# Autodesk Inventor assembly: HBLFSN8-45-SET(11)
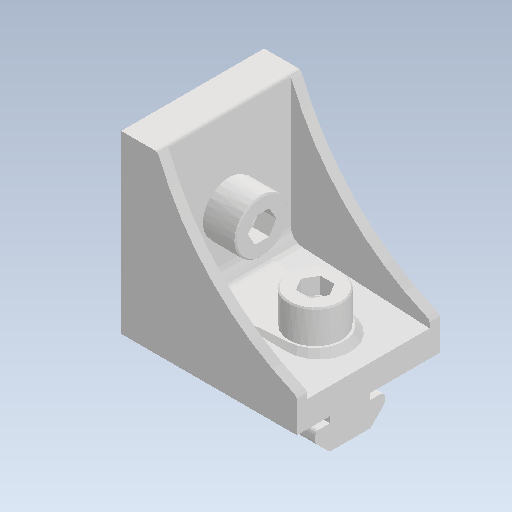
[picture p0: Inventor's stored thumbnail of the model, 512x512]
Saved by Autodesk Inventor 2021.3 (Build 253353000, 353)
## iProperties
Created: 2022-02
Part Number: HBLFSN8-45-SET(11)
Document SubType Name: Assembly
Designer: kengo
Author: kengo
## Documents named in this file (4)
- C:\Users\kengo\Documents\S2S_frame\SDC345\frame_misumi_ver12\HBLFSN8-45-SET(11).iam
- C:\Users\kengo\Documents\S2S_frame\SDC345\frame_misumi_ver12\HBLFSN8-45.ipt
- C:\Users\kengo\Documents\S2S_frame\SDC345\frame_misumi_ver12\HNTT8-8.ipt
- C:\Users\kengo\Documents\S2S_frame\SDC345\frame_misumi_ver12\CBM8-20.ipt
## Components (5 placed, 3 different names)
1. HBLFSN8-45
2. HNTT8-8
3. CBM8-20
4. HNTT8-8:1
5. CBM8-20:1
